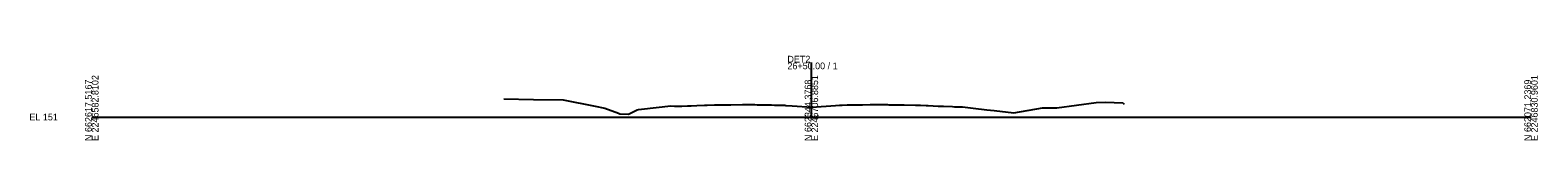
# Model space of a CAD drawing. Extents: x -26 to 603, y -10 to 9526.
# Drawn here: x -26 to 603, y 9490 to 9526 of the extents above; entities that cross this region are included whole.
import ezdxf

# ---------------------------------------------------------------- set-up
doc = ezdxf.new("R2010")
doc.units = 0
for name, color, linetype in [('Default', 7, 'Continuous'), ('Exist Cross Section Cell', 7, 'Continuous'), ('Exist XS Center Line Elevation Label', 7, 'Continuous'), ('Exist XS Ground Line', 7, 'Continuous')]:
    doc.layers.add(name, color=color, linetype=linetype)

msp = doc.modelspace()

# ---------------------------------------------------------------- linework, layer by layer
at = {"layer": 'Exist Cross Section Cell'}
for p, q in [((300, 9500), (300, 9522.73)), ((0, 9500), (300, 9500)), ((300, 9500), (600, 9500))]:
    msp.add_line(p, q, dxfattribs=at)
at = {"layer": 'Exist XS Ground Line'}
for p, q in [((171.75, 9507.58), (184.14, 9507.25)), ((184.14, 9507.25), (196.52, 9507.13)), ((196.52, 9507.13), (209.81, 9504.47)), ((209.81, 9504.47), (213.95, 9503.73)), ((213.95, 9503.73), (219.57, 9501.57)), ((229.19, 9503.23), (241.46, 9504.65)), ((241.46, 9504.65), (242.91, 9504.55)), ((242.91, 9504.55), (243.23, 9504.55)), ((243.23, 9504.55), (244.93, 9504.57)), ((244.93, 9504.57), (245.42, 9504.57)), ((245.42, 9504.57), (246.02, 9504.59)), ((246.02, 9504.59), (248.36, 9504.67)), ((248.36, 9504.67), (249.89, 9504.73)), ((249.89, 9504.73), (252.23, 9504.81)), ((252.23, 9504.81), (255.38, 9504.92)), ((255.38, 9504.92), (256.57, 9504.96)), ((256.57, 9504.96), (259.65, 9505.05)), ((259.65, 9505.05), (260.17, 9505.07)), ((260.17, 9505.07), (261.13, 9505.07)), ((261.13, 9505.07), (261.87, 9505.08)), ((261.87, 9505.08), (262.67, 9505.08)), ((262.67, 9505.08), (266.37, 9505.11)), ((266.37, 9505.11), (271.26, 9505.17)), ((271.26, 9505.17), (271.67, 9505.17)), ((271.67, 9505.17), (272.18, 9505.2)), ((272.18, 9505.2), (273.14, 9505.21)), ((273.14, 9505.21), (273.68, 9505.22)), ((273.68, 9505.22), (276.47, 9505.16)), ((276.47, 9505.16), (277.35, 9505.13)), ((277.35, 9505.13), (282.41, 9505.05)), ((282.41, 9505.05), (282.84, 9505.04)), ((282.84, 9505.04), (283.42, 9505.04)), ((283.42, 9505.04), (284.59, 9505.02)), ((284.59, 9505.02), (286.07, 9504.97)), ((286.07, 9504.97), (287.92, 9504.9)), ((287.92, 9504.9), (288.94, 9504.91)), ((288.94, 9504.91), (289.33, 9504.88)), ((289.33, 9504.88), (291.91, 9504.67)), ((291.91, 9504.67), (300.22, 9504.08)), ((300.22, 9504.08), (310.04, 9504.78)), ((310.04, 9504.78), (311.77, 9504.9)), ((311.77, 9504.9), (312.83, 9504.96)), ((312.83, 9504.96), (314.87, 9505.08)), ((314.87, 9505.08), (315.21, 9505.1)), ((315.21, 9505.1), (316.31, 9505.1)), ((316.31, 9505.1), (316.99, 9505.1)), ((316.99, 9505.1), (319.62, 9505.13)), ((319.62, 9505.13), (320.76, 9505.14)), ((320.76, 9505.14), (321.28, 9505.14)), ((321.28, 9505.14), (324.54, 9505.19)), ((324.54, 9505.19), (325.77, 9505.2)), ((325.77, 9505.2), (326.61, 9505.23)), ((326.61, 9505.23), (327.31, 9505.22)), ((327.31, 9505.22), (331.71, 9505.16)), ((331.71, 9505.16), (332.27, 9505.15)), ((332.27, 9505.15), (336.92, 9505.1)), ((336.92, 9505.1), (338.1, 9505.1)), ((338.1, 9505.1), (338.67, 9505.09)), ((338.67, 9505.09), (343.4, 9504.97)), ((343.4, 9504.97), (345.04, 9504.91)), ((345.04, 9504.91), (345.43, 9504.9)), ((345.43, 9504.9), (347.83, 9504.79)), ((347.83, 9504.79), (348.74, 9504.75)), ((348.74, 9504.75), (352.85, 9504.58)), ((352.85, 9504.58), (354.23, 9504.52)), ((354.23, 9504.52), (355.07, 9504.48)), ((355.07, 9504.48), (358.86, 9504.35)), ((358.86, 9504.35), (359.72, 9504.31)), ((359.72, 9504.31), (360.39, 9504.3)), ((360.39, 9504.3), (362.38, 9504.25)), ((362.38, 9504.25), (363.01, 9504.23)), ((363.01, 9504.23), (367.43, 9503.64)), ((367.43, 9503.64), (373.08, 9502.98)), ((384.32, 9501.71), (396.34, 9503.89)), ((396.34, 9503.89), (402.31, 9503.89)), ((402.31, 9503.89), (418.69, 9506.08)), ((418.69, 9506.08), (422.62, 9506.17)), ((422.62, 9506.17), (429.85, 9505.96)), ((429.85, 9505.96), (430.37, 9505.41)), ((219.57, 9501.57), (220.12, 9501.34)), ((220.12, 9501.34), (223.76, 9501.19)), ((223.76, 9501.19), (227.4, 9502.99)), ((227.4, 9502.99), (227.93, 9503.08)), ((227.93, 9503.08), (229.19, 9503.23)), ((373.08, 9502.98), (376.17, 9502.7)), ((376.17, 9502.7), (384.32, 9501.71))]:
    msp.add_line(p, q, dxfattribs=at)

# ---------------------------------------------------------------- texts
at = {"layer": 'Default'}
msp.add_text('-', height=0.0001, dxfattribs=at).set_placement((0, 9500))
msp.add_text('-', height=0.0001, dxfattribs=at).set_placement((0, 9500))
at = {"layer": 'Exist Cross Section Cell'}
for s, p in [('26+50.00 / 1', (290, 9519.93)), ('DET2', (290, 9522.73)), ('EL 151', (-26, 9498.6))]:
    msp.add_text(s, height=2.8, dxfattribs=at).set_placement(p)
for s, p in [('E 2246582.8102', (2.8, 9490)), ('E 2246706.8851', (302.8, 9490)), ('E 2246830.9601', (602.8, 9490)), ('N 662617.5167', (0, 9490)), ('N 662344.3768', (300, 9490)), ('N 662071.2369', (600, 9490))]:
    msp.add_text(s, height=2.8, rotation=90, dxfattribs=at).set_placement(p)
at = {"layer": 'Exist XS Center Line Elevation Label'}
msp.add_text('155.09', height=1.5, dxfattribs=at).set_placement((296.98, 9499.34))

doc.saveas('drawing.dxf')
